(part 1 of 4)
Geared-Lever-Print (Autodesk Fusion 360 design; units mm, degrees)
parameter "FrameLength" = 640 comment "Fixed existing outer length"
parameter "FrameWidth" = 190 comment "Fixed existing outer width"
parameter "FrameHeight" = 110 comment "Fixed existing height"
parameter "PivotHeight" = 65 comment "Above frame center"
parameter "LeverTravel" = 100 comment "Stable endpoint to endpoint"
parameter "PrintClearance" = 0.3 comment "Prototype diametral running clearance"
base_mesh_feature "Base Mesh Feature"
ground "Pin1"
work_plane "WorkPlane1" AlongDistance -36 ExtraOffset 0
sketch "Flat load-bearing plate" plane through (-36, 0, 0) normal (1, 0, 0) x axis (0, 0, -1)
  line L1 (-33, -55) -> (-33, -75)
  line L2 (2, -55) -> (-33, -55)
  line L3 (2, 55) -> (2, -55)
  line L4 (-33, 55) -> (2, 55)
  line L5 (-33, 75) -> (-33, 55)
  line L6 (-57, 75) -> (-33, 75)
  line L7 (-57, 32) -> (-57, 75)
  line L8 (-86, 26) -> (-57, 32)
  line L9 (-86, -26) -> (-86, 26)
  line L10 (-57, -32) -> (-86, -26)
  line L11 (-57, -75) -> (-57, -32)
  line L12 (-33, -75) -> (-57, -75)
extrude "Extrude1" new body sketch "Flat load-bearing plate" along normal blind 12
work_plane "WorkPlane2" AlongDistance -37 ExtraOffset 0
sketch "Replaceable bushing seat" plane through (-37, 0, 0) normal (1, 0, 0) x axis (0, 0, -1)
  circle C1 centre (-65, 0) radius 10.15
extrude "Extrude2" cut sketch "Replaceable bushing seat" along normal blind 14
work_plane "WorkPlane3" AlongDistance -37 ExtraOffset 0
sketch "Follower pivot bolt" plane through (-37, 0, 0) normal (1, 0, 0) x axis (0, 0, -1)
  circle C1 centre (-12, -35) radius 2.7
extrude "Extrude3" cut sketch "Follower pivot bolt" along normal blind 14
work_plane "WorkPlane4" AlongDistance -76 ExtraOffset 0
sketch "M5 rail mounting bore" plane through (0, -76, 0) normal (0, 1, 0) x axis (1, 0, 0)
  circle C1 centre (-30, -45) radius 2.7
extrude "Extrude4" cut sketch "M5 rail mounting bore" along normal blind 22
work_plane "WorkPlane5" AlongDistance -55 ExtraOffset 0
sketch "Rail screw tool and washer access" plane through (0, -55, 0) normal (0, 1, 0) x axis (1, 0, 0)
  circle C1 centre (-30, -45) radius 5.3
extrude "Extrude5" cut sketch "Rail screw tool and washer access" along normal blind 12
work_plane "WorkPlane6" AlongDistance 54 ExtraOffset 0
sketch "M5 rail mounting bore (1)" plane through (0, 54, 0) normal (0, 1, 0) x axis (1, 0, 0)
  circle C1 centre (-30, -45) radius 2.7
extrude "Extrude6" cut sketch "M5 rail mounting bore (1)" along normal blind 22
work_plane "WorkPlane7" AlongDistance 43 ExtraOffset 0
sketch "Rail screw tool and washer access (1)" plane through (0, 43, 0) normal (0, 1, 0) x axis (1, 0, 0)
  circle C1 centre (-30, -45) radius 5.3
extrude "Extrude7" cut sketch "Rail screw tool and washer access (1)" along normal blind 12
work_plane "WorkPlane8" AlongDistance -37 ExtraOffset 0
sketch "Spring crossblock attachment" plane through (-37, 0, 0) normal (1, 0, 0) x axis (0, 0, -1)
  circle C1 centre (-44, -59) radius 1.7
extrude "Extrude8" cut sketch "Spring crossblock attachment" along normal blind 14
work_plane "WorkPlane9" AlongDistance -37 ExtraOffset 0
sketch "Spring crossblock attachment (1)" plane through (-37, 0, 0) normal (1, 0, 0) x axis (0, 0, -1)
  circle C1 centre (-44, -51) radius 1.7
extrude "Extrude9" cut sketch "Spring crossblock attachment (1)" along normal blind 14
work_plane "WorkPlane1" AlongDistance 24 ExtraOffset 0
sketch "Flat load-bearing plate" plane through (24, 0, 0) normal (1, 0, 0) x axis (0, 0, -1)
  line L1 (-33, -55) -> (-33, -75)
  line L2 (2, -55) -> (-33, -55)
  line L3 (2, 55) -> (2, -55)
  line L4 (-33, 55) -> (2, 55)
  line L5 (-33, 75) -> (-33, 55)
  line L6 (-57, 75) -> (-33, 75)
  line L7 (-57, 32) -> (-57, 75)
  line L8 (-86, 26) -> (-57, 32)
  line L9 (-86, -26) -> (-86, 26)
  line L10 (-57, -32) -> (-86, -26)
  line L11 (-57, -75) -> (-57, -32)
  line L12 (-33, -75) -> (-57, -75)
extrude "Extrude1" new body sketch "Flat load-bearing plate" along normal blind 12
work_plane "WorkPlane2" AlongDistance 23 ExtraOffset 0
sketch "Replaceable bushing seat" plane through (23, 0, 0) normal (1, 0, 0) x axis (0, 0, -1)
  circle C1 centre (-65, 0) radius 10.15
extrude "Extrude2" cut sketch "Replaceable bushing seat" along normal blind 14
work_plane "WorkPlane3" AlongDistance 23 ExtraOffset 0
sketch "Follower pivot bolt" plane through (23, 0, 0) normal (1, 0, 0) x axis (0, 0, -1)
  circle C1 centre (-12, -35) radius 2.7
extrude "Extrude3" cut sketch "Follower pivot bolt" along normal blind 14
work_plane "WorkPlane4" AlongDistance -76 ExtraOffset 0
sketch "M5 rail mounting bore" plane through (0, -76, 0) normal (0, 1, 0) x axis (1, 0, 0)
  circle C1 centre (30, -45) radius 2.7
extrude "Extrude4" cut sketch "M5 rail mounting bore" along normal blind 22
work_plane "WorkPlane5" AlongDistance -55 ExtraOffset 0
sketch "Rail screw tool and washer access" plane through (0, -55, 0) normal (0, 1, 0) x axis (1, 0, 0)
  circle C1 centre (30, -45) radius 5.3
extrude "Extrude5" cut sketch "Rail screw tool and washer access" along normal blind 12
work_plane "WorkPlane6" AlongDistance 54 ExtraOffset 0
sketch "M5 rail mounting bore (1)" plane through (0, 54, 0) normal (0, 1, 0) x axis (1, 0, 0)
  circle C1 centre (30, -45) radius 2.7
extrude "Extrude6" cut sketch "M5 rail mounting bore (1)" along normal blind 22
work_plane "WorkPlane7" AlongDistance 43 ExtraOffset 0
sketch "Rail screw tool and washer access (1)" plane through (0, 43, 0) normal (0, 1, 0) x axis (1, 0, 0)
  circle C1 centre (30, -45) radius 5.3
extrude "Extrude7" cut sketch "Rail screw tool and washer access (1)" along normal blind 12
work_plane "WorkPlane8" AlongDistance 23 ExtraOffset 0
sketch "Spring crossblock attachment" plane through (23, 0, 0) normal (1, 0, 0) x axis (0, 0, -1)
  circle C1 centre (-44, -59) radius 1.7
extrude "Extrude8" cut sketch "Spring crossblock attachment" along normal blind 14
work_plane "WorkPlane9" AlongDistance 23 ExtraOffset 0
sketch "Spring crossblock attachment (1)" plane through (23, 0, 0) normal (1, 0, 0) x axis (0, 0, -1)
  circle C1 centre (-44, -51) radius 1.7
extrude "Extrude9" cut sketch "Spring crossblock attachment (1)" along normal blind 14
work_plane "WorkPlane1" AlongDistance -36 ExtraOffset 0
sketch "Replaceable journal body" plane through (-36, 0, 0) normal (1, 0, 0) x axis (0, 0, -1)
  circle C1 centre (-65, 0) radius 10.05
extrude "Extrude1" new body sketch "Replaceable journal body" along normal blind 12 bodies "P03 Left flanged journal bush"
work_plane "WorkPlane2" AlongDistance -37.2 ExtraOffset 0
sketch "Axial thrust flange" plane through (-37.2, 0, 0) normal (1, 0, 0) x axis (0, 0, -1)
  circle C1 centre (-65, 0) radius 12.75
extrude "Extrude2" add sketch "Axial thrust flange" along normal blind 1.2
work_plane "WorkPlane3" AlongDistance -38 ExtraOffset 0
sketch "Running journal bore" plane through (-38, 0, 0) normal (1, 0, 0) x axis (0, 0, -1)
  circle C1 centre (-65, 0) radius 6.15
extrude "Extrude3" cut sketch "Running journal bore" along normal blind 15
work_plane "WorkPlane1" AlongDistance 24 ExtraOffset 0
sketch "Replaceable journal body" plane through (24, 0, 0) normal (1, 0, 0) x axis (0, 0, -1)
  circle C1 centre (-65, 0) radius 10.05
extrude "Extrude1" new body sketch "Replaceable journal body" along normal blind 12 bodies "P04 Right flanged journal bush"
work_plane "WorkPlane2" AlongDistance 36 ExtraOffset 0
sketch "Axial thrust flange" plane through (36, 0, 0) normal (1, 0, 0) x axis (0, 0, -1)
  circle C1 centre (-65, 0) radius 12.75
extrude "Extrude2" add sketch "Axial thrust flange" along normal blind 1.2
work_plane "WorkPlane3" AlongDistance 23 ExtraOffset 0
sketch "Running journal bore" plane through (23, 0, 0) normal (1, 0, 0) x axis (0, 0, -1)
  circle C1 centre (-65, 0) radius 6.15
extrude "Extrude3" cut sketch "Running journal bore" along normal blind 15
work_plane "WorkPlane1" AlongDistance -39.35 ExtraOffset 0
sketch "Axial cap" plane through (-39.35, 0, 0) normal (1, 0, 0) x axis (0, 0, -1)
  circle C1 centre (-65, 0) radius 10
extrude "Extrude1" new body sketch "Axial cap" along normal blind 2 bodies "P06 Shaft retaining cap"
work_plane "WorkPlane2" AlongDistance -39.5 ExtraOffset 0
sketch "M3 cap screw" plane through (-39.5, 0, 0) normal (1, 0, 0) x axis (0, 0, -1)
  circle C1 centre (-65, 0) radius 1.7
extrude "Extrude2" cut sketch "M3 cap screw" along normal blind 2.4
work_plane "WorkPlane1" AlongDistance -7 ExtraOffset 0
sketch "Main lever hub" plane through (-7, 0, 0) normal (1, 0, 0) x axis (0, 0, -1)
  circle C1 centre (-65, 0) radius 22
extrude "Extrude1" new body sketch "Main lever hub" along normal blind 14 bodies "P07 Integral lever rotor and cam carrier"
work_plane "WorkPlane2" AlongDistance -7 ExtraOffset 0
sketch "Continuous reinforced lever stem" plane through (-7, 0, 0) normal (1, 0, 0) x axis (0, 0, -1)
  line L1 (-60, 14) -> (-60, -14)
  line L2 (-95, 11) -> (-60, 14)
  line L3 (-150, 7) -> (-95, 11)
  line L4 (-195, 7) -> (-150, 7)
  line L5 (-195, -7) -> (-195, 7)
  line L6 (-150, -7) -> (-195, -7)
  line L7 (-95, -11) -> (-150, -7)
  line L8 (-60, -14) -> (-95, -11)
extrude "Extrude2" add sketch "Continuous reinforced lever stem" along normal blind 14
work_plane "WorkPlane3" AlongDistance -7 ExtraOffset 0
sketch "Integrated cam carrier fan" plane through (-7, 0, 0) normal (1, 0, 0) x axis (0, 0, -1)
  line L1 (-44.5, 35.507) -> (-65, 0)
  line L2 (-42.6698, 34.3855) -> (-44.5, 35.507)
  line L3 (-40.9008, 33.1697) -> (-42.6698, 34.3855)
  line L4 (-39.1979, 31.863) -> (-40.9008, 33.1697)
  line L5 (-37.5656, 30.4689) -> (-39.1979, 31.863)
  line L6 (-36.0086, 28.9914) -> (-37.5656, 30.4689)
  line L7 (-34.5311, 27.4344) -> (-36.0086, 28.9914)
  line L8 (-33.137, 25.8021) -> (-34.5311, 27.4344)
  line L9 (-31.8303, 24.0992) -> (-33.137, 25.8021)
  line L10 (-30.6145, 22.3302) -> (-31.8303, 24.0992)
  line L11 (-29.493, 20.5) -> (-30.6145, 22.3302)
  line L12 (-28.4687, 18.6136) -> (-29.493, 20.5)
  line L13 (-27.5446, 16.6762) -> (-28.4687, 18.6136)
  line L14 (-26.7232, 14.6931) -> (-27.5446, 16.6762)
  line L15 (-26.0067, 12.6697) -> (-26.7232, 14.6931)
  line L16 (-25.397, 10.6116) -> (-26.0067, 12.6697)
  line L17 (-24.8959, 8.5244) -> (-25.397, 10.6116)
  line L18 (-24.5048, 6.4138) -> (-24.8959, 8.5244)
  line L19 (-24.2246, 4.2857) -> (-24.5048, 6.4138)
  line L20 (-24.0562, 2.1458) -> (-24.2246, 4.2857)
  line L21 (-24, 0) -> (-24.0562, 2.1458)
  line L22 (-24.0562, -2.1458) -> (-24, 0)
  line L23 (-24.2246, -4.2857) -> (-24.0562, -2.1458)
  line L24 (-24.5048, -6.4138) -> (-24.2246, -4.2857)
  line L25 (-24.8959, -8.5244) -> (-24.5048, -6.4138)
  line L26 (-25.397, -10.6116) -> (-24.8959, -8.5244)
  line L27 (-26.0067, -12.6697) -> (-25.397, -10.6116)
  line L28 (-26.7232, -14.6931) -> (-26.0067, -12.6697)
  line L29 (-27.5446, -16.6762) -> (-26.7232, -14.6931)
  line L30 (-28.4687, -18.6136) -> (-27.5446, -16.6762)
  line L31 (-29.493, -20.5) -> (-28.4687, -18.6136)
  line L32 (-30.6145, -22.3302) -> (-29.493, -20.5)
  line L33 (-31.8303, -24.0992) -> (-30.6145, -22.3302)
  line L34 (-33.137, -25.8021) -> (-31.8303, -24.0992)
  line L35 (-34.5311, -27.4344) -> (-33.137, -25.8021)
  line L36 (-36.0086, -28.9914) -> (-34.5311, -27.4344)
  line L37 (-37.5656, -30.4689) -> (-36.0086, -28.9914)
  line L38 (-39.1979, -31.863) -> (-37.5656, -30.4689)
  line L39 (-40.9008, -33.1697) -> (-39.1979, -31.863)
  line L40 (-42.6698, -34.3855) -> (-40.9008, -33.1697)
  line L41 (-44.5, -35.507) -> (-42.6698, -34.3855)
  line L42 (-65, 0) -> (-44.5, -35.507)
extrude "Extrude3" add sketch "Integrated cam carrier fan" along normal blind 14
work_plane "WorkPlane4" AlongDistance -23.6 ExtraOffset 0
sketch "Integral axial locating hub" plane through (-23.6, 0, 0) normal (1, 0, 0) x axis (0, 0, -1)
  circle C1 centre (-65, 0) radius 10
work_plane "WorkPlane5" AlongDistance -24 ExtraOffset 0
sketch "D shaft socket" plane through (-24, 0, 0) normal (1, 0, 0) x axis (0, 0, -1)
  line L1 (-69.6247, 6.65) -> (-60.3753, 6.65)
  arc A1 centre (-65, 0) radius 8.1 clockwise from (-60.3753, 6.65) to (-69.6247, 6.65)
extrude "Extrude5" cut sketch "D shaft socket" along normal blind 48
work_plane "WorkPlane6" AlongDistance 0.3 ExtraOffset 0
sketch "Cam M3 insert pocket" plane through (0.3, 0, 0) normal (1, 0, 0) x axis (0, 0, -1)
  circle C1 centre (-39.5442, 25.4558) radius 2
extrude "Extrude6" cut sketch "Cam M3 insert pocket" along normal blind 6.8
work_plane "WorkPlane7" AlongDistance 0.3 ExtraOffset 0
sketch "Cam M3 insert pocket (1)" plane through (0.3, 0, 0) normal (1, 0, 0) x axis (0, 0, -1)
  circle C1 centre (-29, 0) radius 2
extrude "Extrude7" cut sketch "Cam M3 insert pocket (1)" along normal blind 6.8
work_plane "WorkPlane8" AlongDistance 0.3 ExtraOffset 0
sketch "Cam M3 insert pocket (2)" plane through (0.3, 0, 0) normal (1, 0, 0) x axis (0, 0, -1)
  circle C1 centre (-39.5442, -25.4558) radius 2
extrude "Extrude8" cut sketch "Cam M3 insert pocket (2)" along normal blind 6.8
work_plane "WorkPlane9" AlongDistance -8 ExtraOffset 0
sketch "Grip through bolt" plane through (-8, 0, 0) normal (1, 0, 0) x axis (0, 0, -1)
  circle C1 centre (-180, 0) radius 1.7
extrude "Extrude9" cut sketch "Grip through bolt" along normal blind 16
work_plane "WorkPlane10" AlongDistance -8 ExtraOffset 0
sketch "Grip through bolt (1)" plane through (-8, 0, 0) normal (1, 0, 0) x axis (0, 0, -1)
  circle C1 centre (-190, 0) radius 1.7
extrude "Extrude10" cut sketch "Grip through bolt (1)" along normal blind 16
work_plane "WorkPlane1" AlongDistance 7 ExtraOffset 0
sketch "Roller compensated replaceable cam" plane through (7, 0, 0) normal (1, 0, 0) x axis (0, 0, -1)
  line L1 (-39.4967, 42.2602) -> (-39.6212, 42.3096)
  line L2 (-39.3834, 42.211) -> (-39.4967, 42.2602)
  line L3 (-39.2796, 42.1617) -> (-39.3834, 42.211)
  line L4 (-39.1836, 42.1119) -> (-39.2796, 42.1617)
  line L5 (-39.0932, 42.0608) -> (-39.1836, 42.1119)
  line L6 (-39.0065, 42.0075) -> (-39.0932, 42.0608)
  line L7 (-38.9215, 41.9508) -> (-39.0065, 42.0075)
  line L8 (-38.8363, 41.8895) -> (-38.9215, 41.9508)
  line L9 (-38.7492, 41.8219) -> (-38.8363, 41.8895)
  line L10 (-38.6586, 41.7465) -> (-38.7492, 41.8219)
  line L11 (-38.5633, 41.6619) -> (-38.6586, 41.7465)
  line L12 (-38.4623, 41.5665) -> (-38.5633, 41.6619)
  line L13 (-38.3549, 41.459) -> (-38.4623, 41.5665)
  line L14 (-38.2404, 41.3384) -> (-38.3549, 41.459)
  line L15 (-38.1184, 41.204) -> (-38.2404, 41.3384)
  line L16 (-37.9886, 41.055) -> (-38.1184, 41.204)
  line L17 (-37.8508, 40.8913) -> (-37.9886, 41.055)
  line L18 (-37.7045, 40.7127) -> (-37.8508, 40.8913)
  line L19 (-37.5496, 40.5196) -> (-37.7045, 40.7127)
  line L20 (-37.3856, 40.3123) -> (-37.5496, 40.5196)
  line L21 (-37.2122, 40.0915) -> (-37.3856, 40.3123)
  line L22 (-37.0289, 39.858) -> (-37.2122, 40.0915)
  line L23 (-36.8353, 39.6128) -> (-37.0289, 39.858)
  line L24 (-36.6306, 39.3571) -> (-36.8353, 39.6128)
  line L25 (-36.4145, 39.0923) -> (-36.6306, 39.3571)
  line L26 (-36.1865, 38.82) -> (-36.4145, 39.0923)
  line L27 (-35.9461, 38.5417) -> (-36.1865, 38.82)
  line L28 (-35.6932, 38.2594) -> (-35.9461, 38.5417)
  line L29 (-35.4277, 37.9751) -> (-35.6932, 38.2594)
  line L30 (-35.15, 37.6908) -> (-35.4277, 37.9751)
  line L31 (-34.8607, 37.4087) -> (-35.15, 37.6908)
  line L32 (-34.5606, 37.1307) -> (-34.8607, 37.4087)
  line L33 (-34.2512, 36.859) -> (-34.5606, 37.1307)
  line L34 (-33.934, 36.5953) -> (-34.2512, 36.859)
  line L35 (-33.6109, 36.341) -> (-33.934, 36.5953)
  line L36 (-33.2841, 36.0975) -> (-33.6109, 36.341)
  line L37 (-32.9558, 35.8655) -> (-33.2841, 36.0975)
  line L38 (-32.6282, 35.6454) -> (-32.9558, 35.8655)
  line L39 (-32.3036, 35.4375) -> (-32.6282, 35.6454)
  line L40 (-31.984, 35.2415) -> (-32.3036, 35.4375)
  line L41 (-31.6712, 35.057) -> (-31.984, 35.2415)
  line L42 (-31.3671, 34.8833) -> (-31.6712, 35.057)
  line L43 (-31.073, 34.7197) -> (-31.3671, 34.8833)
  line L44 (-30.7902, 34.5655) -> (-31.073, 34.7197)
  line L45 (-30.52, 34.4197) -> (-30.7902, 34.5655)
  line L46 (-30.263, 34.2816) -> (-30.52, 34.4197)
  line L47 (-30.0201, 34.1506) -> (-30.263, 34.2816)
  line L48 (-29.7919, 34.0259) -> (-30.0201, 34.1506)
  line L49 (-29.5787, 33.9071) -> (-29.7919, 34.0259)
  line L50 (-29.3807, 33.7939) -> (-29.5787, 33.9071)
  line L51 (-29.1982, 33.6858) -> (-29.3807, 33.7939)
  line L52 (-29.0309, 33.5827) -> (-29.1982, 33.6858)
  line L53 (-28.8786, 33.4843) -> (-29.0309, 33.5827)
  line L54 (-28.7406, 33.3906) -> (-28.8786, 33.4843)
  line L55 (-28.6164, 33.3013) -> (-28.7406, 33.3906)
  line L56 (-28.5047, 33.2161) -> (-28.6164, 33.3013)
  line L57 (-28.4046, 33.1346) -> (-28.5047, 33.2161)
  line L58 (-28.3144, 33.0563) -> (-28.4046, 33.1346)
  line L59 (-28.2327, 32.9802) -> (-28.3144, 33.0563)
  line L60 (-28.1577, 32.9052) -> (-28.2327, 32.9802)
  line L61 (-28.0879, 32.8301) -> (-28.1577, 32.9052)
  line L62 (-28.0214, 32.7532) -> (-28.0879, 32.8301)
  line L63 (-27.9569, 32.6728) -> (-28.0214, 32.7532)
  line L64 (-27.893, 32.5869) -> (-27.9569, 32.6728)
  line L65 (-27.8285, 32.4936) -> (-27.893, 32.5869)
  line L66 (-27.7627, 32.3911) -> (-27.8285, 32.4936)
  line L67 (-27.6947, 32.2776) -> (-27.7627, 32.3911)
  line L68 (-27.6241, 32.1514) -> (-27.6947, 32.2776)
  line L69 (-27.5507, 32.0113) -> (-27.6241, 32.1514)
  line L70 (-27.4742, 31.8562) -> (-27.5507, 32.0113)
  line L71 (-27.3945, 31.6853) -> (-27.4742, 31.8562)
  line L72 (-27.3113, 31.4981) -> (-27.3945, 31.6853)
  line L73 (-27.2245, 31.2943) -> (-27.3113, 31.4981)
  line L74 (-27.1338, 31.074) -> (-27.2245, 31.2943)
  line L75 (-27.0388, 30.8373) -> (-27.1338, 31.074)
  line L76 (-26.939, 30.5847) -> (-27.0388, 30.8373)
  line L77 (-26.8337, 30.3166) -> (-26.939, 30.5847)
  line L78 (-26.7223, 30.034) -> (-26.8337, 30.3166)
  line L79 (-26.6038, 29.7375) -> (-26.7223, 30.034)
  line L80 (-26.4775, 29.4284) -> (-26.6038, 29.7375)
  line L81 (-26.3424, 29.1079) -> (-26.4775, 29.4284)
  line L82 (-26.1977, 28.7772) -> (-26.3424, 29.1079)
  line L83 (-26.0425, 28.4382) -> (-26.1977, 28.7772)
  line L84 (-25.8761, 28.0925) -> (-26.0425, 28.4382)
  line L85 (-25.6981, 27.7422) -> (-25.8761, 28.0925)
  line L86 (-25.5084, 27.3893) -> (-25.6981, 27.7422)
  line L87 (-25.3069, 27.0362) -> (-25.5084, 27.3893)
  line L88 (-25.0943, 26.6851) -> (-25.3069, 27.0362)
  line L89 (-24.8713, 26.3382) -> (-25.0943, 26.6851)
  line L90 (-24.6392, 25.9976) -> (-24.8713, 26.3382)
  line L91 (-24.3995, 25.6653) -> (-24.6392, 25.9976)
  line L92 (-24.1539, 25.3428) -> (-24.3995, 25.6653)
  line L93 (-23.9045, 25.0314) -> (-24.1539, 25.3428)
  line L94 (-23.6532, 24.7321) -> (-23.9045, 25.0314)
  line L95 (-23.4022, 24.4455) -> (-23.6532, 24.7321)
  line L96 (-23.1534, 24.1718) -> (-23.4022, 24.4455)
  line L97 (-22.9088, 23.9111) -> (-23.1534, 24.1718)
  line L98 (-22.6701, 23.6631) -> (-22.9088, 23.9111)
  line L99 (-22.4387, 23.4276) -> (-22.6701, 23.6631)
  line L100 (-22.2162, 23.204) -> (-22.4387, 23.4276)
  line L101 (-22.0036, 22.9918) -> (-22.2162, 23.204)
  line L102 (-21.8021, 22.7907) -> (-22.0036, 22.9918)
  line L103 (-21.6123, 22.6001) -> (-21.8021, 22.7907)
  line L104 (-21.435, 22.4197) -> (-21.6123, 22.6001)
  line L105 (-21.2706, 22.2491) -> (-21.435, 22.4197)
  line L106 (-21.1193, 22.088) -> (-21.2706, 22.2491)
  line L107 (-20.9813, 21.9362) -> (-21.1193, 22.088)
  line L108 (-20.8565, 21.7934) -> (-20.9813, 21.9362)
  line L109 (-20.7443, 21.6594) -> (-20.8565, 21.7934)
  line L110 (-20.6444, 21.5337) -> (-20.7443, 21.6594)
  line L111 (-20.556, 21.4159) -> (-20.6444, 21.5337)
  line L112 (-20.478, 21.3055) -> (-20.556, 21.4159)
  line L113 (-20.4094, 21.2014) -> (-20.478, 21.3055)
  line L114 (-20.349, 21.1027) -> (-20.4094, 21.2014)
  line L115 (-20.2954, 21.0079) -> (-20.349, 21.1027)
  line L116 (-20.2475, 20.9154) -> (-20.2954, 21.0079)
  line L117 (-20.2039, 20.8234) -> (-20.2475, 20.9154)
  line L118 (-20.1637, 20.7297) -> (-20.2039, 20.8234)
  line L119 (-20.126, 20.6321) -> (-20.1637, 20.7297)
  line L120 (-20.0901, 20.5286) -> (-20.126, 20.6321)
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extrude "Extrude1" new body sketch "Roller compensated replaceable cam" along normal blind 8 bodies "P08 Cam 7 gates - stable endpoints"
work_plane "WorkPlane2" AlongDistance 6.9 ExtraOffset 0
sketch "Cam screw clearance" plane through (6.9, 0, 0) normal (1, 0, 0) x axis (0, 0, -1)
  circle C1 centre (-39.5442, 25.4558) radius 1.7
extrude "Extrude2" cut sketch "Cam screw clearance" along normal blind 8.2
work_plane "WorkPlane3" AlongDistance 12 ExtraOffset 0
sketch "Cam head recess" plane through (12, 0, 0) normal (1, 0, 0) x axis (0, 0, -1)
  circle C1 centre (-39.5442, 25.4558) radius 3.1
extrude "Extrude3" cut sketch "Cam head recess" along normal blind 3.1
work_plane "WorkPlane4" AlongDistance 6.9 ExtraOffset 0
sketch "Cam screw clearance (1)" plane through (6.9, 0, 0) normal (1, 0, 0) x axis (0, 0, -1)
  circle C1 centre (-29, 0) radius 1.7
extrude "Extrude4" cut sketch "Cam screw clearance (1)" along normal blind 8.2
work_plane "WorkPlane5" AlongDistance 12 ExtraOffset 0
sketch "Cam head recess (1)" plane through (12, 0, 0) normal (1, 0, 0) x axis (0, 0, -1)
  circle C1 centre (-29, 0) radius 3.1
extrude "Extrude5" cut sketch "Cam head recess (1)" along normal blind 3.1
work_plane "WorkPlane6" AlongDistance 6.9 ExtraOffset 0
sketch "Cam screw clearance (2)" plane through (6.9, 0, 0) normal (1, 0, 0) x axis (0, 0, -1)
  circle C1 centre (-39.5442, -25.4558) radius 1.7
extrude "Extrude6" cut sketch "Cam screw clearance (2)" along normal blind 8.2
work_plane "WorkPlane7" AlongDistance 12 ExtraOffset 0
sketch "Cam head recess (2)" plane through (12, 0, 0) normal (1, 0, 0) x axis (0, 0, -1)
  circle C1 centre (-39.5442, -25.4558) radius 3.1
extrude "Extrude7" cut sketch "Cam head recess (2)" along normal blind 3.1
work_plane "WorkPlane1" AlongDistance 7 ExtraOffset 0
sketch "Roller compensated replaceable cam" plane through (7, 0, 0) normal (1, 0, 0) x axis (0, 0, -1)
  line L1 (-40.6423, 42.8316) -> (-40.8055, 42.9534)
  line L2 (-40.4783, 42.705) -> (-40.6423, 42.8316)
  line L3 (-40.3132, 42.5736) -> (-40.4783, 42.705)
  line L4 (-40.1469, 42.4372) -> (-40.3132, 42.5736)
  line L5 (-39.9791, 42.2958) -> (-40.1469, 42.4372)
  line L6 (-39.8097, 42.1493) -> (-39.9791, 42.2958)
  line L7 (-39.6386, 41.9977) -> (-39.8097, 42.1493)
  line L8 (-39.4656, 41.8411) -> (-39.6386, 41.9977)
  line L9 (-39.2906, 41.6794) -> (-39.4656, 41.8411)
  line L10 (-39.1134, 41.5128) -> (-39.2906, 41.6794)
  line L11 (-38.9338, 41.3413) -> (-39.1134, 41.5128)
  line L12 (-38.7519, 41.165) -> (-38.9338, 41.3413)
  line L13 (-38.5674, 40.9842) -> (-38.7519, 41.165)
  line L14 (-38.3803, 40.7991) -> (-38.5674, 40.9842)
  line L15 (-38.1904, 40.6097) -> (-38.3803, 40.7991)
  line L16 (-37.9976, 40.4164) -> (-38.1904, 40.6097)
  line L17 (-37.8019, 40.2195) -> (-37.9976, 40.4164)
  line L18 (-37.6031, 40.0191) -> (-37.8019, 40.2195)
  line L19 (-37.4011, 39.8157) -> (-37.6031, 40.0191)
  line L20 (-37.1958, 39.6094) -> (-37.4011, 39.8157)
  line L21 (-36.9872, 39.4008) -> (-37.1958, 39.6094)
  line L22 (-36.7753, 39.19) -> (-36.9872, 39.4008)
  line L23 (-36.5599, 38.9775) -> (-36.7753, 39.19)
  line L24 (-36.3411, 38.7636) -> (-36.5599, 38.9775)
  line L25 (-36.1189, 38.5488) -> (-36.3411, 38.7636)
  line L26 (-35.8933, 38.3333) -> (-36.1189, 38.5488)
  line L27 (-35.6644, 38.1177) -> (-35.8933, 38.3333)
  line L28 (-35.4322, 37.9021) -> (-35.6644, 38.1177)
  line L29 (-35.197, 37.6871) -> (-35.4322, 37.9021)
  line L30 (-34.9588, 37.473) -> (-35.197, 37.6871)
  line L31 (-34.7178, 37.2602) -> (-34.9588, 37.473)
  line L32 (-34.4743, 37.0489) -> (-34.7178, 37.2602)
  line L33 (-34.2286, 36.8395) -> (-34.4743, 37.0489)
  line L34 (-33.9808, 36.6322) -> (-34.2286, 36.8395)
  line L35 (-33.7314, 36.4274) -> (-33.9808, 36.6322)
  line L36 (-33.4806, 36.2252) -> (-33.7314, 36.4274)
  line L37 (-33.2289, 36.0258) -> (-33.4806, 36.2252)
  line L38 (-32.9765, 35.8294) -> (-33.2289, 36.0258)
  line L39 (-32.7239, 35.6361) -> (-32.9765, 35.8294)
  line L40 (-32.4714, 35.446) -> (-32.7239, 35.6361)
  line L41 (-32.2195, 35.259) -> (-32.4714, 35.446)
  line L42 (-31.9685, 35.0753) -> (-32.2195, 35.259)
  line L43 (-31.7188, 34.8948) -> (-31.9685, 35.0753)
  line L44 (-31.4708, 34.7175) -> (-31.7188, 34.8948)
  line L45 (-31.2249, 34.5432) -> (-31.4708, 34.7175)
  line L46 (-30.9813, 34.3719) -> (-31.2249, 34.5432)
  line L47 (-30.7405, 34.2034) -> (-30.9813, 34.3719)
  line L48 (-30.5027, 34.0377) -> (-30.7405, 34.2034)
  line L49 (-30.2682, 33.8746) -> (-30.5027, 34.0377)
  line L50 (-30.0373, 33.7139) -> (-30.2682, 33.8746)
  line L51 (-29.8103, 33.5555) -> (-30.0373, 33.7139)
  line L52 (-29.5875, 33.3992) -> (-29.8103, 33.5555)
  line L53 (-29.3689, 33.2448) -> (-29.5875, 33.3992)
  line L54 (-29.1548, 33.0923) -> (-29.3689, 33.2448)
  line L55 (-28.9455, 32.9414) -> (-29.1548, 33.0923)
  line L56 (-28.7409, 32.7921) -> (-28.9455, 32.9414)
  line L57 (-28.5413, 32.644) -> (-28.7409, 32.7921)
  line L58 (-28.3468, 32.4972) -> (-28.5413, 32.644)
  line L59 (-28.1574, 32.3515) -> (-28.3468, 32.4972)
  line L60 (-27.9732, 32.2068) -> (-28.1574, 32.3515)
  line L61 (-27.7942, 32.0628) -> (-27.9732, 32.2068)
  line L62 (-27.6204, 31.9196) -> (-27.7942, 32.0628)
  line L63 (-27.4518, 31.7769) -> (-27.6204, 31.9196)
  line L64 (-27.2884, 31.6347) -> (-27.4518, 31.7769)
  line L65 (-27.1301, 31.4927) -> (-27.2884, 31.6347)
  line L66 (-26.9767, 31.351) -> (-27.1301, 31.4927)
  line L67 (-26.8282, 31.2092) -> (-26.9767, 31.351)
  line L68 (-26.6843, 31.0673) -> (-26.8282, 31.2092)
  line L69 (-26.545, 30.925) -> (-26.6843, 31.0673)
  line L70 (-26.4101, 30.7822) -> (-26.545, 30.925)
  line L71 (-26.2793, 30.6387) -> (-26.4101, 30.7822)
  line L72 (-26.1524, 30.4942) -> (-26.2793, 30.6387)
  line L73 (-26.0293, 30.3485) -> (-26.1524, 30.4942)
  line L74 (-25.9096, 30.2013) -> (-26.0293, 30.3485)
  line L75 (-25.7932, 30.0524) -> (-25.9096, 30.2013)
  line L76 (-25.6797, 29.9015) -> (-25.7932, 30.0524)
  line L77 (-25.5691, 29.7482) -> (-25.6797, 29.9015)
  line L78 (-25.461, 29.5923) -> (-25.5691, 29.7482)
  line L79 (-25.3553, 29.4334) -> (-25.461, 29.5923)
  line L80 (-25.2517, 29.2713) -> (-25.3553, 29.4334)
  line L81 (-25.15, 29.1057) -> (-25.2517, 29.2713)
  line L82 (-25.0502, 28.9363) -> (-25.15, 29.1057)
  line L83 (-24.9519, 28.7628) -> (-25.0502, 28.9363)
  line L84 (-24.855, 28.5849) -> (-24.9519, 28.7628)
  line L85 (-24.7595, 28.4024) -> (-24.855, 28.5849)
  line L86 (-24.665, 28.2152) -> (-24.7595, 28.4024)
  line L87 (-24.5716, 28.023) -> (-24.665, 28.2152)
  line L88 (-24.4791, 27.8257) -> (-24.5716, 28.023)
  line L89 (-24.3873, 27.6231) -> (-24.4791, 27.8257)
  line L90 (-24.2961, 27.4152) -> (-24.3873, 27.6231)
  line L91 (-24.2054, 27.2019) -> (-24.2961, 27.4152)
  line L92 (-24.115, 26.9832) -> (-24.2054, 27.2019)
  line L93 (-24.0247, 26.7591) -> (-24.115, 26.9832)
  line L94 (-23.9346, 26.5296) -> (-24.0247, 26.7591)
  line L95 (-23.8442, 26.2947) -> (-23.9346, 26.5296)
  line L96 (-23.7536, 26.0546) -> (-23.8442, 26.2947)
  line L97 (-23.6625, 25.8094) -> (-23.7536, 26.0546)
  line L98 (-23.5707, 25.5592) -> (-23.6625, 25.8094)
  line L99 (-23.478, 25.3041) -> (-23.5707, 25.5592)
  line L100 (-23.3842, 25.0444) -> (-23.478, 25.3041)
  line L101 (-23.2891, 24.7802) -> (-23.3842, 25.0444)
  line L102 (-23.1926, 24.5118) -> (-23.2891, 24.7802)
  line L103 (-23.0943, 24.2394) -> (-23.1926, 24.5118)
  line L104 (-22.9942, 23.9633) -> (-23.0943, 24.2394)
  line L105 (-22.8919, 23.6838) -> (-22.9942, 23.9633)
  line L106 (-22.7873, 23.4012) -> (-22.8919, 23.6838)
  line L107 (-22.6803, 23.1157) -> (-22.7873, 23.4012)
  line L108 (-22.5706, 22.8278) -> (-22.6803, 23.1157)
  line L109 (-22.4581, 22.5379) -> (-22.5706, 22.8278)
  line L110 (-22.3428, 22.2461) -> (-22.4581, 22.5379)
  line L111 (-22.2245, 21.953) -> (-22.3428, 22.2461)
  line L112 (-22.1031, 21.659) -> (-22.2245, 21.953)
  line L113 (-21.9788, 21.3644) -> (-22.1031, 21.659)
  line L114 (-21.8513, 21.0696) -> (-21.9788, 21.3644)
  line L115 (-21.7209, 20.7751) -> (-21.8513, 21.0696)
  line L116 (-21.5876, 20.4811) -> (-21.7209, 20.7751)
  line L117 (-21.4516, 20.1882) -> (-21.5876, 20.4811)
  line L118 (-21.3129, 19.8966) -> (-21.4516, 20.1882)
  line L119 (-21.1718, 19.6067) -> (-21.3129, 19.8966)
  line L120 (-21.0286, 19.3189) -> (-21.1718, 19.6067)
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extrude "Extrude1" new body sketch "Roller compensated replaceable cam" along normal blind 8 bodies "P08 Cam 5 gates - stable endpoints"
work_plane "WorkPlane2" AlongDistance 6.9 ExtraOffset 0
sketch "Cam screw clearance" plane through (6.9, 0, 0) normal (1, 0, 0) x axis (0, 0, -1)
  circle C1 centre (-39.5442, 25.4558) radius 1.7
extrude "Extrude2" cut sketch "Cam screw clearance" along normal blind 8.2
work_plane "WorkPlane3" AlongDistance 12 ExtraOffset 0
sketch "Cam head recess" plane through (12, 0, 0) normal (1, 0, 0) x axis (0, 0, -1)
  circle C1 centre (-39.5442, 25.4558) radius 3.1
extrude "Extrude3" cut sketch "Cam head recess" along normal blind 3.1
work_plane "WorkPlane4" AlongDistance 6.9 ExtraOffset 0
sketch "Cam screw clearance (1)" plane through (6.9, 0, 0) normal (1, 0, 0) x axis (0, 0, -1)
  circle C1 centre (-29, 0) radius 1.7
extrude "Extrude4" cut sketch "Cam screw clearance (1)" along normal blind 8.2
work_plane "WorkPlane5" AlongDistance 12 ExtraOffset 0
sketch "Cam head recess (1)" plane through (12, 0, 0) normal (1, 0, 0) x axis (0, 0, -1)
  circle C1 centre (-29, 0) radius 3.1
extrude "Extrude5" cut sketch "Cam head recess (1)" along normal blind 3.1
work_plane "WorkPlane6" AlongDistance 6.9 ExtraOffset 0
sketch "Cam screw clearance (2)" plane through (6.9, 0, 0) normal (1, 0, 0) x axis (0, 0, -1)
  circle C1 centre (-39.5442, -25.4558) radius 1.7
extrude "Extrude6" cut sketch "Cam screw clearance (2)" along normal blind 8.2
work_plane "WorkPlane7" AlongDistance 12 ExtraOffset 0
sketch "Cam head recess (2)" plane through (12, 0, 0) normal (1, 0, 0) x axis (0, 0, -1)
  circle C1 centre (-39.5442, -25.4558) radius 3.1
extrude "Extrude7" cut sketch "Cam head recess (2)" along normal blind 3.1
work_plane "WorkPlane1" AlongDistance 7 ExtraOffset 0
sketch "Roller compensated replaceable cam" plane through (7, 0, 0) normal (1, 0, 0) x axis (0, 0, -1)
  line L1 (-40.92, 42.0772) -> (-41.1325, 42.2273)
  line L2 (-40.7077, 41.9259) -> (-40.92, 42.0772)
  line L3 (-40.4956, 41.7734) -> (-40.7077, 41.9259)
  line L4 (-40.2838, 41.6199) -> (-40.4956, 41.7734)
  line L5 (-40.0721, 41.4654) -> (-40.2838, 41.6199)
  line L6 (-39.8606, 41.3098) -> (-40.0721, 41.4654)
  line L7 (-39.6492, 41.1532) -> (-39.8606, 41.3098)
  line L8 (-39.4381, 40.9957) -> (-39.6492, 41.1532)
  line L9 (-39.2271, 40.8372) -> (-39.4381, 40.9957)
  line L10 (-39.0163, 40.6779) -> (-39.2271, 40.8372)
  line L11 (-38.8057, 40.5176) -> (-39.0163, 40.6779)
  line L12 (-38.5952, 40.3566) -> (-38.8057, 40.5176)
  line L13 (-38.3849, 40.1947) -> (-38.5952, 40.3566)
  line L14 (-38.1747, 40.032) -> (-38.3849, 40.1947)
  line L15 (-37.9647, 39.8686) -> (-38.1747, 40.032)
  line L16 (-37.7549, 39.7045) -> (-37.9647, 39.8686)
  line L17 (-37.5452, 39.5397) -> (-37.7549, 39.7045)
  line L18 (-37.3357, 39.3742) -> (-37.5452, 39.5397)
  line L19 (-37.1263, 39.2081) -> (-37.3357, 39.3742)
  line L20 (-36.9171, 39.0413) -> (-37.1263, 39.2081)
  line L21 (-36.7081, 38.874) -> (-36.9171, 39.0413)
  line L22 (-36.4992, 38.7061) -> (-36.7081, 38.874)
  line L23 (-36.2905, 38.5376) -> (-36.4992, 38.7061)
  line L24 (-36.082, 38.3687) -> (-36.2905, 38.5376)
  line L25 (-35.8737, 38.1992) -> (-36.082, 38.3687)
  line L26 (-35.6656, 38.0292) -> (-35.8737, 38.1992)
  line L27 (-35.4577, 37.8588) -> (-35.6656, 38.0292)
  line L28 (-35.25, 37.688) -> (-35.4577, 37.8588)
  line L29 (-35.0425, 37.5167) -> (-35.25, 37.688)
  line L30 (-34.8352, 37.3451) -> (-35.0425, 37.5167)
  line L31 (-34.6282, 37.173) -> (-34.8352, 37.3451)
  line L32 (-34.4215, 37.0006) -> (-34.6282, 37.173)
  line L33 (-34.215, 36.8278) -> (-34.4215, 37.0006)
  line L34 (-34.0088, 36.6547) -> (-34.215, 36.8278)
  line L35 (-33.8028, 36.4812) -> (-34.0088, 36.6547)
  line L36 (-33.5972, 36.3074) -> (-33.8028, 36.4812)
  line L37 (-33.392, 36.1333) -> (-33.5972, 36.3074)
  line L38 (-33.187, 35.9589) -> (-33.392, 36.1333)
  line L39 (-32.9825, 35.7842) -> (-33.187, 35.9589)
  line L40 (-32.7783, 35.6093) -> (-32.9825, 35.7842)
  line L41 (-32.5745, 35.434) -> (-32.7783, 35.6093)
  line L42 (-32.3711, 35.2584) -> (-32.5745, 35.434)
  line L43 (-32.1682, 35.0826) -> (-32.3711, 35.2584)
  line L44 (-31.9657, 34.9065) -> (-32.1682, 35.0826)
  line L45 (-31.7637, 34.7302) -> (-31.9657, 34.9065)
  line L46 (-31.5623, 34.5535) -> (-31.7637, 34.7302)
  line L47 (-31.3613, 34.3766) -> (-31.5623, 34.5535)
  line L48 (-31.1609, 34.1994) -> (-31.3613, 34.3766)
  line L49 (-30.9611, 34.0219) -> (-31.1609, 34.1994)
  line L50 (-30.7619, 33.8442) -> (-30.9611, 34.0219)
  line L51 (-30.5634, 33.6662) -> (-30.7619, 33.8442)
  line L52 (-30.3654, 33.4878) -> (-30.5634, 33.6662)
  line L53 (-30.1682, 33.3092) -> (-30.3654, 33.4878)
  line L54 (-29.9717, 33.1303) -> (-30.1682, 33.3092)
  line L55 (-29.7759, 32.9511) -> (-29.9717, 33.1303)
  line L56 (-29.5809, 32.7715) -> (-29.7759, 32.9511)
  line L57 (-29.3866, 32.5916) -> (-29.5809, 32.7715)
  line L58 (-29.1932, 32.4114) -> (-29.3866, 32.5916)
  line L59 (-29.0007, 32.2308) -> (-29.1932, 32.4114)
  line L60 (-28.809, 32.0499) -> (-29.0007, 32.2308)
  line L61 (-28.6182, 31.8686) -> (-28.809, 32.0499)
  line L62 (-28.4284, 31.6869) -> (-28.6182, 31.8686)
  line L63 (-28.2395, 31.5048) -> (-28.4284, 31.6869)
  line L64 (-28.0516, 31.3224) -> (-28.2395, 31.5048)
  line L65 (-27.8647, 31.1395) -> (-28.0516, 31.3224)
  line L66 (-27.6789, 30.9562) -> (-27.8647, 31.1395)
  line L67 (-27.4942, 30.7724) -> (-27.6789, 30.9562)
  line L68 (-27.3106, 30.5882) -> (-27.4942, 30.7724)
  line L69 (-27.1281, 30.4035) -> (-27.3106, 30.5882)
  line L70 (-26.9468, 30.2184) -> (-27.1281, 30.4035)
  line L71 (-26.7667, 30.0327) -> (-26.9468, 30.2184)
  line L72 (-26.5878, 29.8465) -> (-26.7667, 30.0327)
  line L73 (-26.4102, 29.6599) -> (-26.5878, 29.8465)
  line L74 (-26.2338, 29.4727) -> (-26.4102, 29.6599)
  line L75 (-26.0588, 29.2849) -> (-26.2338, 29.4727)
  line L76 (-25.8851, 29.0966) -> (-26.0588, 29.2849)
  line L77 (-25.7127, 28.9078) -> (-25.8851, 29.0966)
  line L78 (-25.5418, 28.7183) -> (-25.7127, 28.9078)
  line L79 (-25.3723, 28.5283) -> (-25.5418, 28.7183)
  line L80 (-25.2042, 28.3376) -> (-25.3723, 28.5283)
  line L81 (-25.0376, 28.1464) -> (-25.2042, 28.3376)
  line L82 (-24.8725, 27.9545) -> (-25.0376, 28.1464)
  line L83 (-24.7089, 27.762) -> (-24.8725, 27.9545)
  line L84 (-24.5469, 27.5688) -> (-24.7089, 27.762)
  line L85 (-24.3864, 27.375) -> (-24.5469, 27.5688)
  line L86 (-24.2275, 27.1805) -> (-24.3864, 27.375)
  line L87 (-24.0703, 26.9854) -> (-24.2275, 27.1805)
  line L88 (-23.9146, 26.7895) -> (-24.0703, 26.9854)
  line L89 (-23.7607, 26.593) -> (-23.9146, 26.7895)
  line L90 (-23.6084, 26.3958) -> (-23.7607, 26.593)
  line L91 (-23.4578, 26.1978) -> (-23.6084, 26.3958)
  line L92 (-23.3089, 25.9992) -> (-23.4578, 26.1978)
  line L93 (-23.1618, 25.7998) -> (-23.3089, 25.9992)
  line L94 (-23.0164, 25.5997) -> (-23.1618, 25.7998)
  line L95 (-22.8728, 25.3988) -> (-23.0164, 25.5997)
  line L96 (-22.7309, 25.1972) -> (-22.8728, 25.3988)
  line L97 (-22.5909, 24.9949) -> (-22.7309, 25.1972)
  line L98 (-22.4527, 24.7917) -> (-22.5909, 24.9949)
  line L99 (-22.3163, 24.5879) -> (-22.4527, 24.7917)
  line L100 (-22.1817, 24.3832) -> (-22.3163, 24.5879)
  line L101 (-22.049, 24.1778) -> (-22.1817, 24.3832)
  line L102 (-21.9182, 23.9716) -> (-22.049, 24.1778)
  line L103 (-21.7892, 23.7646) -> (-21.9182, 23.9716)
  line L104 (-21.6622, 23.5568) -> (-21.7892, 23.7646)
  line L105 (-21.537, 23.3482) -> (-21.6622, 23.5568)
  line L106 (-21.4137, 23.1388) -> (-21.537, 23.3482)
  line L107 (-21.2923, 22.9286) -> (-21.4137, 23.1388)
  line L108 (-21.1728, 22.7176) -> (-21.2923, 22.9286)
  line L109 (-21.0553, 22.5058) -> (-21.1728, 22.7176)
  line L110 (-20.9397, 22.2931) -> (-21.0553, 22.5058)
  line L111 (-20.8259, 22.0796) -> (-20.9397, 22.2931)
  line L112 (-20.7142, 21.8653) -> (-20.8259, 22.0796)
  line L113 (-20.6043, 21.6502) -> (-20.7142, 21.8653)
  line L114 (-20.4964, 21.4342) -> (-20.6043, 21.6502)
  line L115 (-20.3904, 21.2174) -> (-20.4964, 21.4342)
  line L116 (-20.2863, 20.9997) -> (-20.3904, 21.2174)
  line L117 (-20.1842, 20.7812) -> (-20.2863, 20.9997)
  line L118 (-20.0839, 20.5618) -> (-20.1842, 20.7812)
  line L119 (-19.9856, 20.3416) -> (-20.0839, 20.5618)
  line L120 (-19.8892, 20.1205) -> (-19.9856, 20.3416)
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extrude "Extrude1" new body sketch "Roller compensated replaceable cam" along normal blind 8 bodies "P08 Cam 3 gates - stable endpoints"
work_plane "WorkPlane2" AlongDistance 6.9 ExtraOffset 0
sketch "Cam screw clearance" plane through (6.9, 0, 0) normal (1, 0, 0) x axis (0, 0, -1)
  circle C1 centre (-39.5442, 25.4558) radius 1.7
extrude "Extrude2" cut sketch "Cam screw clearance" along normal blind 8.2
work_plane "WorkPlane3" AlongDistance 12 ExtraOffset 0
sketch "Cam head recess" plane through (12, 0, 0) normal (1, 0, 0) x axis (0, 0, -1)
  circle C1 centre (-39.5442, 25.4558) radius 3.1
extrude "Extrude3" cut sketch "Cam head recess" along normal blind 3.1
work_plane "WorkPlane4" AlongDistance 6.9 ExtraOffset 0
sketch "Cam screw clearance (1)" plane through (6.9, 0, 0) normal (1, 0, 0) x axis (0, 0, -1)
  circle C1 centre (-29, 0) radius 1.7
extrude "Extrude4" cut sketch "Cam screw clearance (1)" along normal blind 8.2
work_plane "WorkPlane5" AlongDistance 12 ExtraOffset 0
sketch "Cam head recess (1)" plane through (12, 0, 0) normal (1, 0, 0) x axis (0, 0, -1)
  circle C1 centre (-29, 0) radius 3.1
extrude "Extrude5" cut sketch "Cam head recess (1)" along normal blind 3.1
work_plane "WorkPlane6" AlongDistance 6.9 ExtraOffset 0
sketch "Cam screw clearance (2)" plane through (6.9, 0, 0) normal (1, 0, 0) x axis (0, 0, -1)
  circle C1 centre (-39.5442, -25.4558) radius 1.7
extrude "Extrude6" cut sketch "Cam screw clearance (2)" along normal blind 8.2
work_plane "WorkPlane7" AlongDistance 12 ExtraOffset 0
sketch "Cam head recess (2)" plane through (12, 0, 0) normal (1, 0, 0) x axis (0, 0, -1)
  circle C1 centre (-39.5442, -25.4558) radius 3.1
extrude "Extrude7" cut sketch "Cam head recess (2)" along normal blind 3.1
work_plane "WorkPlane1" AlongDistance 0 ExtraOffset 0
sketch "Palm grip smooth contour" plane through (0, 0, 0) normal (1, 0, 0) x axis (0, 0, -1)
  curve K1 (-225, 0) -> (-165, 12)
  line L1 (-225, 0) -> (-165, 0)
  line L2 (-165, 12) -> (-165, 0)
revolve "Revolve1" sketch "Palm grip smooth contour" AlongAngle 360 bodies "P09 Grip insert half"
work_plane "WorkPlane2" AlongDistance 0 ExtraOffset 0
sketch "Split on print bed face" plane through (0, 0, 0) normal (1, 0, 0) x axis (0, 0, -1)
  line L1 (-160, 30) -> (-160, -30)
  line L2 (-230, 30) -> (-160, 30)
  line L3 (-230, -30) -> (-230, 30)
  line L4 (-160, -30) -> (-230, -30)
extrude "Extrude1" cut sketch "Split on print bed face" along normal blind 30
work_plane "WorkPlane3" AlongDistance -7.2 ExtraOffset 0
sketch "Keyed stem socket" plane through (-7.2, 0, 0) normal (1, 0, 0) x axis (0, 0, -1)
  line L1 (-164, 7.2) -> (-164, -7.2)
  line L2 (-196, 7.2) -> (-164, 7.2)
  line L3 (-196, -7.2) -> (-196, 7.2)
  line L4 (-164, -7.2) -> (-196, -7.2)
extrude "Extrude2" cut sketch "Keyed stem socket" along normal blind 14.4
work_plane "WorkPlane4" AlongDistance -13.9 ExtraOffset 0
sketch "M3 grip heat set" plane through (-13.9, 0, 0) normal (1, 0, 0) x axis (0, 0, -1)
  circle C1 centre (-180, 0) radius 2
extrude "Extrude3" cut sketch "M3 grip heat set" along normal blind 6.8
work_plane "WorkPlane5" AlongDistance -13.9 ExtraOffset 0
sketch "M3 grip heat set (1)" plane through (-13.9, 0, 0) normal (1, 0, 0) x axis (0, 0, -1)
  circle C1 centre (-190, 0) radius 2
extrude "Extrude4" cut sketch "M3 grip heat set (1)" along normal blind 6.8
work_plane "WorkPlane1" AlongDistance 0 ExtraOffset 0
sketch "Palm grip smooth contour" plane through (0, 0, 0) normal (1, 0, 0) x axis (0, 0, -1)
  curve K1 (-225, 0) -> (-165, 12)
  line L1 (-225, 0) -> (-165, 0)
  line L2 (-165, 12) -> (-165, 0)
revolve "Revolve1" sketch "Palm grip smooth contour" AlongAngle 360 bodies "P10 Grip screw half"
work_plane "WorkPlane2" AlongDistance -30 ExtraOffset 0
sketch "Split on print bed face" plane through (-30, 0, 0) normal (1, 0, 0) x axis (0, 0, -1)
  line L1 (-160, 30) -> (-160, -30)
  line L2 (-230, 30) -> (-160, 30)
  line L3 (-230, -30) -> (-230, 30)
  line L4 (-160, -30) -> (-230, -30)
extrude "Extrude1" cut sketch "Split on print bed face" along normal blind 30
work_plane "WorkPlane3" AlongDistance -7.2 ExtraOffset 0
sketch "Keyed stem socket" plane through (-7.2, 0, 0) normal (1, 0, 0) x axis (0, 0, -1)
  line L1 (-164, 7.2) -> (-164, -7.2)
  line L2 (-196, 7.2) -> (-164, 7.2)
  line L3 (-196, -7.2) -> (-196, 7.2)
  line L4 (-164, -7.2) -> (-196, -7.2)
extrude "Extrude2" cut sketch "Keyed stem socket" along normal blind 14.4
work_plane "WorkPlane4" AlongDistance -0.1 ExtraOffset 0
sketch "Grip screw bore" plane through (-0.1, 0, 0) normal (1, 0, 0) x axis (0, 0, -1)
  circle C1 centre (-180, 0) radius 1.7
extrude "Extrude3" cut sketch "Grip screw bore" along normal blind 26
work_plane "WorkPlane5" AlongDistance 12.5 ExtraOffset 0
sketch "Recessed grip screw head" plane through (12.5, 0, 0) normal (1, 0, 0) x axis (0, 0, -1)
  circle C1 centre (-180, 0) radius 3.1
extrude "Extrude4" cut sketch "Recessed grip screw head" along normal blind 14
work_plane "WorkPlane6" AlongDistance -0.1 ExtraOffset 0
sketch "Grip screw bore (1)" plane through (-0.1, 0, 0) normal (1, 0, 0) x axis (0, 0, -1)
  circle C1 centre (-190, 0) radius 1.7
extrude "Extrude5" cut sketch "Grip screw bore (1)" along normal blind 26
work_plane "WorkPlane7" AlongDistance 12.5 ExtraOffset 0
sketch "Recessed grip screw head (1)" plane through (12.5, 0, 0) normal (1, 0, 0) x axis (0, 0, -1)
  circle C1 centre (-190, 0) radius 3.1
extrude "Extrude6" cut sketch "Recessed grip screw head (1)" along normal blind 14
work_plane "WorkPlane1" AlongDistance 4 ExtraOffset 0
sketch "First strong flat cheek" plane through (4, 0, 0) normal (1, 0, 0) x axis (0, 0, -1)
  line L1 (-6, -5) -> (-6, -61)
  line L2 (-7, 0) -> (-6, -5)
  line L3 (-17, 0) -> (-7, 0)
  line L4 (-18, -5) -> (-17, 0)
  line L5 (-18, -61) -> (-18, -5)
  line L6 (-6, -61) -> (-18, -61)
extrude "Extrude1" new body sketch "First strong flat cheek" along normal blind 3 bodies "P11 Forked roller follower"
work_plane "WorkPlane2" AlongDistance 4 ExtraOffset 0
sketch "Spring tail bridge" plane through (4, 0, 0) normal (1, 0, 0) x axis (0, 0, -1)
  line L1 (-6, -49) -> (-6, -61)
  line L2 (-18, -49) -> (-6, -49)
  line L3 (-18, -61) -> (-18, -49)
  line L4 (-6, -61) -> (-18, -61)
extrude "Extrude2" add sketch "Spring tail bridge" along normal blind 16
work_plane "WorkPlane3" AlongDistance 17 ExtraOffset 0
sketch "Second supporting cheek" plane through (17, 0, 0) normal (1, 0, 0) x axis (0, 0, -1)
  line L1 (-6, -5) -> (-6, -61)
  line L2 (-7, 0) -> (-6, -5)
  line L3 (-17, 0) -> (-7, 0)
  line L4 (-18, -5) -> (-17, 0)
  line L5 (-18, -61) -> (-18, -5)
  line L6 (-6, -61) -> (-18, -61)
extrude "Extrude3" add sketch "Second supporting cheek" along normal blind 3
work_plane "WorkPlane4" AlongDistance 4 ExtraOffset 0
sketch "Rounded roller cheek" plane through (4, 0, 0) normal (1, 0, 0) x axis (0, 0, -1)
  circle C1 centre (-12, 0) radius 6
extrude "Extrude4" add sketch "Rounded roller cheek" along normal blind 3
work_plane "WorkPlane5" AlongDistance 17 ExtraOffset 0
sketch "Rounded roller cheek (1)" plane through (17, 0, 0) normal (1, 0, 0) x axis (0, 0, -1)
  circle C1 centre (-12, 0) radius 6
extrude "Extrude5" add sketch "Rounded roller cheek (1)" along normal blind 3
work_plane "WorkPlane6" AlongDistance 3.9 ExtraOffset 0
sketch "Smooth pivot sleeve bore" plane through (3.9, 0, 0) normal (1, 0, 0) x axis (0, 0, -1)
  circle C1 centre (-12, -35) radius 4.15
extrude "Extrude6" cut sketch "Smooth pivot sleeve bore" along normal blind 16.2
work_plane "WorkPlane7" AlongDistance 3.9 ExtraOffset 0
sketch "Roller axle holes" plane through (3.9, 0, 0) normal (1, 0, 0) x axis (0, 0, -1)
  circle C1 centre (-12, 0) radius 1.7
extrude "Extrude7" cut sketch "Roller axle holes" along normal blind 16.2
work_plane "WorkPlane8" AlongDistance 3.9 ExtraOffset 0
sketch "Roller M3 nut recess" plane through (3.9, 0, 0) normal (1, 0, 0) x axis (0, 0, -1)
  line L1 (-14.9, 1.6743) -> (-12, 3.3486)
  line L2 (-14.9, -1.6743) -> (-14.9, 1.6743)
  line L3 (-12, -3.3486) -> (-14.9, -1.6743)
  line L4 (-9.1, -1.6743) -> (-12, -3.3486)
  line L5 (-9.1, 1.6743) -> (-9.1, -1.6743)
  line L6 (-12, 3.3486) -> (-9.1, 1.6743)
extrude "Extrude8" cut sketch "Roller M3 nut recess" along normal blind 1.6
work_plane "WorkPlane9" AlongDistance 18 ExtraOffset 0
sketch "Spring tail locating pilot" plane through (0, 0, 18) normal (0, 0, 1) x axis (1, 0, 0)
  circle C1 centre (12, -55) radius 1.8
extrude "Extrude9" add sketch "Spring tail locating pilot" along normal blind 2
work_plane "WorkPlane1" AlongDistance -24 ExtraOffset 0
sketch "Captured spring reaction block" plane through (-24, 0, 0) normal (1, 0, 0) x axis (0, 0, -1)
  line L1 (-38, -44) -> (-38, -66)
  line L2 (-52, -44) -> (-38, -44)
  line L3 (-52, -66) -> (-52, -44)
  line L4 (-38, -66) -> (-52, -66)
extrude "Extrude1" new body sketch "Captured spring reaction block" along normal blind 48
work_plane "WorkPlane2" AlongDistance -24.1 ExtraOffset 0
sketch "Left M3 insert with screw tip relief" plane through (-24.1, 0, 0) normal (1, 0, 0) x axis (0, 0, -1)
  circle C1 centre (-44, -59) radius 2
extrude "Extrude2" cut sketch "Left M3 insert with screw tip relief" along normal blind 8.8
work_plane "WorkPlane3" AlongDistance 15.3 ExtraOffset 0
sketch "Right M3 insert with screw tip relief" plane through (15.3, 0, 0) normal (1, 0, 0) x axis (0, 0, -1)
  circle C1 centre (-44, -59) radius 2
extrude "Extrude3" cut sketch "Right M3 insert with screw tip relief" along normal blind 8.8
work_plane "WorkPlane4" AlongDistance -24.1 ExtraOffset 0
sketch "Left M3 insert with screw tip relief (1)" plane through (-24.1, 0, 0) normal (1, 0, 0) x axis (0, 0, -1)
  circle C1 centre (-44, -51) radius 2
extrude "Extrude4" cut sketch "Left M3 insert with screw tip relief (1)" along normal blind 8.8
work_plane "WorkPlane5" AlongDistance 15.3 ExtraOffset 0
sketch "Right M3 insert with screw tip relief (1)" plane through (15.3, 0, 0) normal (1, 0, 0) x axis (0, 0, -1)
  circle C1 centre (-44, -51) radius 2
extrude "Extrude5" cut sketch "Right M3 insert with screw tip relief (1)" along normal blind 8.8
work_plane "WorkPlane6" AlongDistance 37.9 ExtraOffset 0
sketch "M4 preload adjuster" plane through (0, 0, 37.9) normal (0, 0, 1) x axis (1, 0, 0)
  circle C1 centre (12, -55) radius 2.2
extrude "Extrude6" cut sketch "M4 preload adjuster" along normal blind 14.2
work_plane "WorkPlane7" AlongDistance 37.9 ExtraOffset 0
sketch "Spring-side loaded retained M4 nut" plane through (0, 0, 37.9) normal (0, 0, 1) x axis (1, 0, 0)
  line L1 (14.1362, -51.3) -> (16.2724, -55)
  line L2 (9.8638, -51.3) -> (14.1362, -51.3)
  line L3 (7.7276, -55) -> (9.8638, -51.3)
  line L4 (9.8638, -58.7) -> (7.7276, -55)
  line L5 (14.1362, -58.7) -> (9.8638, -58.7)
  line L6 (16.2724, -55) -> (14.1362, -58.7)
extrude "Extrude7" cut sketch "Spring-side loaded retained M4 nut" along normal blind 3.5
work_plane "WorkPlane8" AlongDistance 37.9 ExtraOffset 0
sketch "Spring cup guide bolts" plane through (0, 0, 37.9) normal (0, 0, 1) x axis (1, 0, 0)
  circle C1 centre (5, -55) radius 1.7
extrude "Extrude8" cut sketch "Spring cup guide bolts" along normal blind 14.2
work_plane "WorkPlane9" AlongDistance 37.9 ExtraOffset 0
sketch "Spring cup guide bolts (1)" plane through (0, 0, 37.9) normal (0, 0, 1) x axis (1, 0, 0)
  circle C1 centre (19, -55) radius 1.7
extrude "Extrude9" cut sketch "Spring cup guide bolts (1)" along normal blind 14.2
work_plane "WorkPlane11" AlongDistance -18 ExtraOffset 0
sketch "Dedicated thick stop lug" plane through (-18, 0, 0) normal (1, 0, 0) x axis (0, 0, -1)
  line L1 (-72, 5) -> (-72, -5)
  line L2 (-95, 5) -> (-72, 5)
  line L3 (-95, -5) -> (-95, 5)
  line L4 (-72, -5) -> (-95, -5)
extrude "Extrude11" add sketch "Dedicated thick stop lug" along normal blind 11.5
work_plane "WorkPlane12" AlongDistance -18 ExtraOffset 0
sketch "Rounded stop contact" plane through (-18, 0, 0) normal (1, 0, 0) x axis (0, 0, -1)
  circle C1 centre (-95, 0) radius 5
extrude "Extrude12" add sketch "Rounded stop contact" along normal blind 11.5
work_plane "WorkPlane10" AlongDistance -36 ExtraOffset 0
sketch "Broad stop support ear" plane through (-36, 0, 0) normal (1, 0, 0) x axis (0, 0, -1)
  line L1 (-60, -20) -> (-60, -44)
  line L2 (-90, -20) -> (-60, -20)
  line L3 (-90, -44) -> (-90, -20)
  line L4 (-60, -44) -> (-90, -44)
extrude "Extrude10" add sketch "Broad stop support ear" along normal blind 12
work_plane "WorkPlane11" AlongDistance -24 ExtraOffset 0
sketch "Integrated steel-core end stop" plane through (-24, 0, 0) normal (1, 0, 0) x axis (0, 0, -1)
  circle C1 centre (-79.6754, -33.9652) radius 6
extrude "Extrude11" add sketch "Integrated steel-core end stop" along normal blind 15
work_plane "WorkPlane12" AlongDistance -36.1 ExtraOffset 0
